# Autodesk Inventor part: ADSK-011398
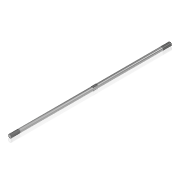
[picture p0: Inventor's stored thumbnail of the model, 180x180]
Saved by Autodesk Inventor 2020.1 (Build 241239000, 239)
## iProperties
Created: 2000-01
Part Number: ADSK-011398
Material: Acier doux
Description: SHFT-T,RC,HX,04-20,177,013,013,ROD,CONNECTING
Document SubType Name: Modeling
Designer: sspink
Density: 7.86 g/cm^3
Appearance: Chrom - poliert
Mass: 276.762 g
Surface Area: 142.603 cm^2
Volume: 35.2114 cm^3
Control State: 0
Checked Out: False
Master: False
Shininess: 0.0
Length Units: 11269
Angle Units: 11279
Time Units: 11290
Mass Units: 11283
Length Display Precision: 3
Angle Display Precision: 2
Compacted: True
Cutlength: 17.75
Material Desc: ROUND,CD,0.438 DIA
Material_number: A098976
Dimensions: 10x10x450 mm
Mass: 0,277 kg
DocNumber: ADSK-011398.ipt
Folder: 01 - Themengebiete\Simplification\01 - Packaging machine\
VDS_Category: 3D Komponenten
Density: 0.0
Volumn: 0.0
Area: 0.0
PropertySet Name: Model Information
Author: sspink
Revision Number: -
Title: shaft
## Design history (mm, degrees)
chamfer "Fase1" distance "d14" = 1; stored, may be unused: second distance "d15" = 2, angle "d16" = 45 deg
node "Solide1"
  node "Extrusion1" dims "d1" = 450, "d2" = 0
  node "Extrusion2" dims "d6" = 12.5, "d7" = 0
sketch "Sketch1"
  geometry: C1 r 5 at (0, 0); 1 further point
  constraints: 1 centre point, 1 coincident
  dimensions: "d0" = 10 diameter of C1
workplane "Work Plane1"
sketch "Sketch2"
  geometry: L1 (-3, 4)-(3, 4); L2 (-3, -4)-(3, -4); L3 (0, 0)-(0, -5); L4 (0, 0)-(0, 5); A1 r 5 centre (0, 0) between (-3, 4) and (3, 4) reference
  constraints: 8 end point, 6 point on circle, 2 vertical, 1 coincident, 1 horizontal, 1 parallel, 1 vertical alignment, 2 other
  dimensions: "d8" = 8 distance between parallel lines of L2 L1; "d9" = 4 distance from line of A1.centre L1 (= 0.5 x d8)
feature "Gewinde1" dims "d10" = 25, "d11" = 0
feature "Gewinde2" dims "d12" = 25, "d13" = 0
node "Corps solides"
node "Corps surfaciques"
other parameters: "d3" = 219.075
